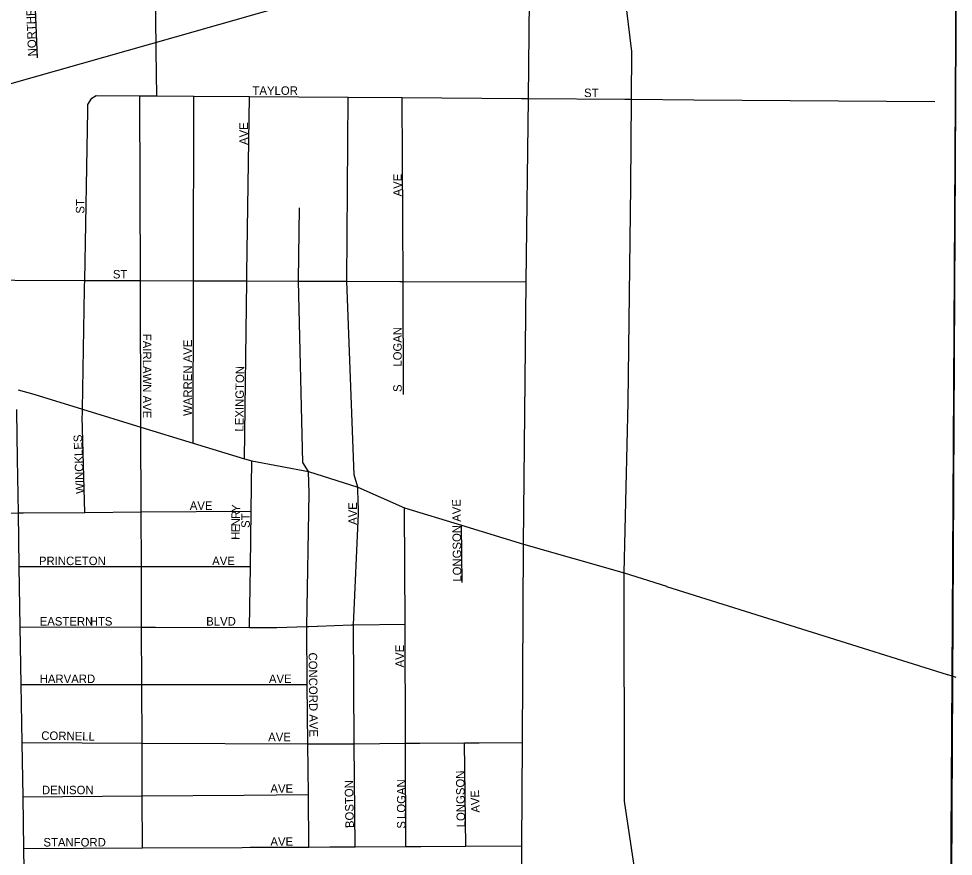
# Model space of a CAD drawing. Extents: x 1857828 to 2277390, y 930619 to 1324581.
# Drawn here: x 2081409 to 2086916, y 1224059 to 1228997 of the extents above; entities that cross this region are included whole.
import ezdxf

# ---------------------------------------------------------------- set-up
doc = ezdxf.new("R2010")
doc.units = 0
for name, color, linetype in [('GM_X_City_Street', 7, 'Continuous'), ('GM_X_City_Street_Text', 7, 'Continuous'), ('GM_X_Corporation', 7, 'Continuous'), ('GM_X_Rail_Line', 7, 'Continuous'), ('GM_X_Township', 7, 'Continuous'), ('GM_X_US_Route', 7, 'Continuous')]:
    doc.layers.add(name, color=color, linetype=linetype)

msp = doc.modelspace()

# ---------------------------------------------------------------- linework, layer by layer
at = {"layer": 'GM_X_City_Street'}
for points in [[(2082219.9, 1228807.4), (2082219.8, 1228819.2), (2082208.7, 1229710.8)], [(2084360.5, 1221282), (2084360.8, 1221334.4), (2084374.2, 1224121.1), (2084377.1, 1224730.6), (2084382.7, 1225899.8), (2084400.3, 1227445.5), (2084412.6, 1228526.1), (2084423.7, 1229496.2)], [(2081519.1, 1228766.4), (2081490.6, 1229485)], [(2082223.2, 1228541.7), (2082219.9, 1228807.4)], [(2081797, 1227401.4), (2081797.3, 1227417), (2081797.9, 1227454), (2081815.6, 1228456.2), (2081815.8, 1228490.3), (2081840, 1228528.3)], [(2081840, 1228528.3), (2081866.1, 1228544.2), (2082122.2, 1228542.4), (2082223.2, 1228541.7), (2082440.4, 1228540.1), (2082768.6, 1228537.8), (2083350.8, 1228533.7), (2083669, 1228531.4), (2084372.7, 1228526.4)], [(2082131.1, 1226090.7), (2082129.3, 1226589.5), (2082126.2, 1227452.9), (2082122.2, 1228542.4)], [(2082437.9, 1226495.1), (2082439.1, 1227451.9), (2082440.4, 1228540.1)], [(2082754.1, 1227496.4), (2082768.6, 1228537.8)], [(2083411, 1226110.5), (2083410, 1226140.4), (2083408, 1226234.7), (2083386, 1226306.9), (2083343, 1227449), (2083350.8, 1228533.7)], [(2083674.2, 1227447.9), (2083669, 1228531.4)], [(2084372.7, 1228526.4), (2084372.8, 1228526.4), (2084412.6, 1228526.1), (2084981.6, 1228522.1)], [(2084981.6, 1228522.1), (2084981.7, 1228522.1), (2085020.3, 1228521.8), (2085387.6, 1228519.2)], [(2085387.6, 1228519.2), (2085387.6, 1228519.2), (2086808.4, 1228509.1)], [(2083058.6, 1227455.3), (2083063.1, 1227880.9)], [(2079292.7, 1227421.3), (2079825.8, 1227444.9), (2080125.9, 1227458.2), (2080153.3, 1227459.4), (2080467.9, 1227458.3), (2080873.7, 1227457), (2081385.9, 1227455.4), (2081792.5, 1227454), (2081797.9, 1227454)], [(2081797.9, 1227454), (2082126.2, 1227452.9), (2082439.1, 1227451.9), (2082753.4, 1227450.9), (2083058.5, 1227449.9), (2083343, 1227449), (2083655.2, 1227447.9), (2083656.8, 1227447.9)], [(2082738.8, 1226403), (2082753.4, 1227450.9), (2082754.1, 1227496.4), (2082754.1, 1227496.4)], [(2083118.9, 1224114), (2083115.8, 1224423.8), (2083112.9, 1224722.5), (2083109.4, 1225071.5), (2083106, 1225413.8), (2083121.2, 1226199.6), (2083117.2, 1226328), (2083083.1, 1226381.1), (2083058.5, 1227449.9), (2083058.6, 1227454.8), (2083058.6, 1227455.3)], [(2081784.1, 1226665.1), (2081784.2, 1226671), (2081784.6, 1226695), (2081797, 1227401.4)], [(2083656.8, 1227447.9), (2083674.2, 1227447.9), (2084400.3, 1227445.5)], [(2083677.5, 1226781.2), (2083674.2, 1227447.9)], [(2081405.4, 1226809), (2081498.2, 1226782.7), (2081784.6, 1226695), (2082129.3, 1226589.5), (2082437.9, 1226495.1), (2082738.8, 1226403), (2082783.2, 1226389.4), (2083117.2, 1226328), (2083408, 1226234.7), (2083682.8, 1226114), (2084017.8, 1226011.5), (2084382.7, 1225899.8)], [(2081468.2, 1222334), (2081460.3, 1222821.1), (2081455.1, 1223142), (2081450.5, 1223426.8), (2081445.5, 1223731.6), (2081439.4, 1224104.6), (2081434.5, 1224409.2), (2081429.3, 1224730.2), (2081423.8, 1225071.1), (2081418.2, 1225412), (2081412.5, 1225767), (2081407.3, 1226084), (2081402.1, 1226402.9), (2081397.6, 1226681.5), (2081397.4, 1226692.4)], [(2081798.9, 1226086.7), (2081783.8, 1226649.7), (2081784.1, 1226665.1)], [(2082769.6, 1225407.9), (2082774.5, 1225766.8), (2082779.1, 1226093.5), (2082783.2, 1226389.4)], [(2079397.4, 1226079.3), (2079735.5, 1226074.6), (2079833.6, 1226073.3), (2080540, 1226078), (2080580, 1226078.3), (2081407.3, 1226084), (2081436.7, 1226084.2), (2081437.2, 1226084.2)], [(2081437.2, 1226084.2), (2081798.9, 1226086.7), (2082131.1, 1226089), (2082779.1, 1226093.5)], [(2082136.6, 1224578), (2082136, 1224727), (2082134.8, 1225071.3), (2082133.6, 1225410.6), (2082132.3, 1225766.9), (2082131.1, 1226089), (2082131.1, 1226090.7), (2082131.1, 1226090.7)], [(2083391, 1224115.5), (2083386.4, 1224723), (2083381.2, 1225423.3), (2083412, 1226080.2), (2083411, 1226110.5)], [(2083691.1, 1224117.2), (2083688.6, 1224725.3), (2083685.7, 1225427.8), (2083682.8, 1226114)], [(2084021.6, 1225672.7), (2084017.8, 1226011.5)], [(2084382.7, 1225899.8), (2084382.7, 1225899.8), (2084976.1, 1225729.3)], [(2081412.5, 1225767), (2082132.3, 1225766.9), (2082774.5, 1225766.8)], [(2084976.1, 1225729.3), (2085226.7, 1225650.6)], [(2085226.7, 1225650.6), (2085226.9, 1225650.5), (2086880.5, 1225131.4)], [(2081418.2, 1225412), (2082133.6, 1225410.6), (2082215.3, 1225410.4), (2082769.6, 1225407.9), (2082929.6, 1225407.1), (2083106, 1225413.8), (2083117.7, 1225414.3), (2083168.3, 1225416)], [(2083168.3, 1225416), (2083169.2, 1225416.1), (2083369.9, 1225423.1), (2083381.2, 1225423.3), (2083685.7, 1225427.8)], [(2086880.5, 1225131.4), (2086882, 1225130.9), (2086907.4, 1225122.9), (2086932.2, 1225115.2)], [(2081423.8, 1225071.1), (2082134.8, 1225071.3), (2083109.4, 1225071.5)], [(2081429.3, 1224730.2), (2082136, 1224727), (2083112.9, 1224722.5), (2083238.9, 1224721.9), (2083244.1, 1224721.9), (2083297.5, 1224722.3)], [(2083297.5, 1224722.3), (2083386.4, 1224723), (2083688.6, 1224725.3), (2083704.5, 1224725.4), (2083772.6, 1224726)], [(2083772.6, 1224726), (2084036.6, 1224728), (2084066.7, 1224728.2), (2084121.7, 1224728.7)], [(2084043.3, 1224119.2), (2084036.6, 1224728)], [(2084121.7, 1224728.7), (2084377.1, 1224730.6)], [(2082138.2, 1224108.5), (2082137.1, 1224415.3), (2082136.6, 1224578), (2082136.6, 1224578)], [(2082735.2, 1224420.5), (2082736.2, 1224420.5), (2083115.8, 1224423.8)], [(2081434.5, 1224409.2), (2082137.1, 1224415.3), (2082735.2, 1224420.5)], [(2081439.4, 1224104.6), (2082138.2, 1224108.5), (2082726.6, 1224111.8), (2082773.2, 1224112.1)], [(2082773.2, 1224112.1), (2083118.9, 1224114), (2083241.5, 1224114.7), (2083302.4, 1224115)], [(2083302.4, 1224115), (2083391, 1224115.5), (2083691.1, 1224117.2), (2083704.9, 1224117.3), (2083778.7, 1224117.7)], [(2083778.7, 1224117.7), (2084043.3, 1224119.2), (2084374.2, 1224121.1)]]:
    msp.add_lwpolyline(points, dxfattribs=at)
at = {"layer": 'GM_X_Corporation'}
msp.add_lwpolyline([(2113906.2, 1245908.9), (2113890.9, 1243217.2), (2113849.1, 1234218.1), (2113829.3, 1229946.4), (2113744.8, 1221267.2), (2112015.1, 1221289.3), (2108462.7, 1221311.6), (2108435.6, 1221318.7), (2108389.2, 1221316.1), (2108204.3, 1221319.4), (2095838.9, 1221294.6), (2094008.8, 1221306.3), (2090317.5, 1221329.8), (2090283.5, 1221329.8), (2090249.5, 1221329.8), (2087936.7, 1221317.6), (2086892.2, 1221272.8), (2087018.7, 1245699), (2100580.4, 1245842), (2107567, 1245842.9)], close=True, dxfattribs=at)
msp.add_lwpolyline([(2087018.7, 1245699), (2086892.2, 1221272.8), (2087936.7, 1221317.6)], dxfattribs=at)
at = {"layer": 'GM_X_Rail_Line'}
msp.add_lwpolyline([(2079138.9, 1227983.5), (2082332, 1228890.3), (2084107.6, 1229395.8), (2084957.7, 1229623.6), (2085547.3, 1229788.8), (2085739.4, 1229842.4), (2085872.8, 1229875.2), (2086003, 1229906.4), (2086097.6, 1229925.5), (2086192.3, 1229943.8)], dxfattribs=at)
at = {"layer": 'GM_X_Township'}
msp.add_lwpolyline([(2086945.4, 1231597.8), (2086907.4, 1225122.9), (2086885, 1221290.7)], dxfattribs=at)
at = {"layer": 'GM_X_US_Route'}
msp.add_lwpolyline([(2086012.9, 1221942.8), (2085781.3, 1222291.6), (2085534.3, 1222655), (2085329.9, 1223057.3), (2085165.6, 1223442.7), (2085059.2, 1223848.6), (2085027.9, 1224055.9), (2084979.3, 1224383.8), (2084976.1, 1225729.3), (2085000.7, 1226736.4), (2085017, 1228008.8), (2085020.3, 1228521.8), (2085022.2, 1228804.1), (2084971.9, 1229224.6), (2084892.8, 1229587.2), (2084842, 1229810.4), (2084797.7, 1230746.9)], dxfattribs=at)

# ---------------------------------------------------------------- texts
at = {"layer": 'GM_X_City_Street_Text'}
for s, rotation, p in [('NORTHRUP ST', 92.412, (2081514.5, 1228775.5)), ('TAYLOR', 0, (2082786.7, 1228547.7)), ('ST', 0, (2084740.3, 1228534.5)), ('AVE', 90, (2082759.7, 1228252.3)), ('AVE', 90, (2083666.1, 1227948.7)), ('ST', 90, (2081796.1, 1227847.5)), ('ST', 0, (2081963.9, 1227465.3)), ('FAIRLAWN AVE', 270, (2082140.5, 1227139.1)), ('LOGAN', 90, (2083666.1, 1226945.5)), ('WARREN AVE', 90, (2082429.7, 1226655.1)), ('LEXINGTON', 89.2842, (2082733.3, 1226562.8)), ('S', 90, (2083666.1, 1226795.9)), ('WINCKLES', 92.3847, (2081796.1, 1226197.1)), ('AVE', 0, (2082417.1, 1226101.3)), ('Y', 87.0481, (2082712.9, 1226086.9)), ('AVE', 90, (2083402.1, 1226012.7)), ('LONGSON AVE', 90.5843, (2084018.1, 1225678.2)), ('R', 89.4173, (2082712.5, 1226047.8)), ('ST', 90, (2082770.9, 1225995.1)), ('N', 89.4112, (2082712.1, 1226003.8)), ('H', 89.4319, (2082711.3, 1225924.6)), ('E', 89.3992, (2082711.7, 1225968.6)), ('PRINCETON', 0, (2081528.3, 1225775.7)), ('AVE', 0, (2082549.1, 1225775.7)), ('EASTERN', 0, (2081532.7, 1225419.3)), ('HTS', 0, (2081827.5, 1225419.3)), ('BLVD', 0, (2082513.9, 1225419.3)), ('CONCORD AVE', 270.579, (2083117.3, 1225260.2)), ('AVE', 90, (2083679.3, 1225172.3)), ('HARVARD', 0, (2081532.7, 1225080.5)), ('AVE', 0, (2082883.5, 1225080.5)), ('CORNELL', 359.1053, (2081541.6, 1224746.1)), ('AVE', 0, (2082879.1, 1224737.3)), ('LONGSON', 90.871, (2084040.1, 1224230.6)), ('AVE', 0, (2082892.3, 1224433.7)), ('BOSTON', 91.0223, (2083384.5, 1224226.1)), ('LOGAN', 90, (2083688.1, 1224279.1)), ('DENISON', 0, (2081545.9, 1224425)), ('AVE', 91.9814, (2084126, 1224317)), ('S', 90, (2083688.1, 1224221.9)), ('STANFORD', 0, (2081554.7, 1224117)), ('AVE', 0, (2082892.3, 1224121.3))]:
    msp.add_text(s, height=50, rotation=rotation, dxfattribs=at).set_placement(p)

doc.saveas('drawing.dxf')
